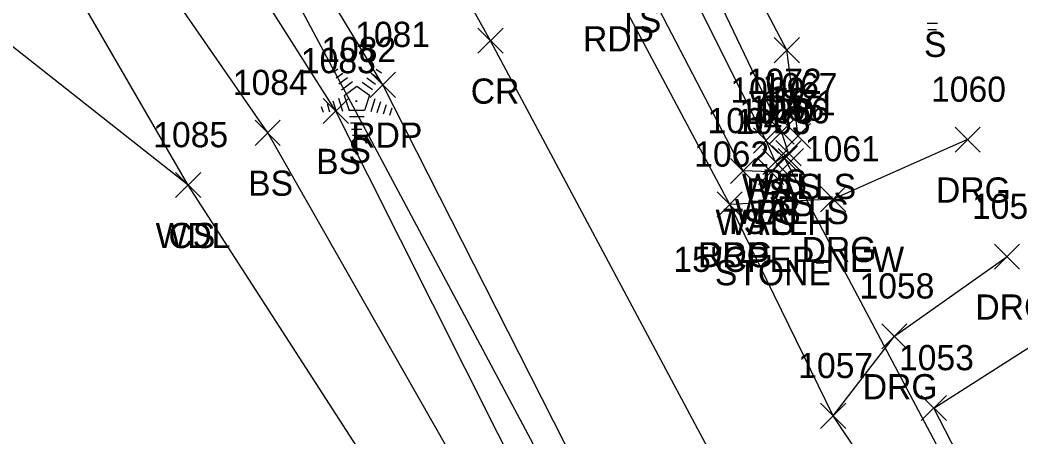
# Model space of a CAD drawing. Extents: x 1501299 to 1502485, y 381423 to 383765.
# Drawn here: x 1501851.9 to 1501931.5, y 382849.9 to 382883 of the extents above; entities that cross this region are included whole.
import ezdxf

# ---------------------------------------------------------------- set-up
doc = ezdxf.new("R2010")
doc.units = 0
for name, color, linetype in [('D_A', 7, 'Continuous'), ('D_C', 7, 'Continuous'), ('D_I', 7, 'Continuous'), ('D_TIC', 7, 'Continuous'), ('DCP', 7, 'Continuous'), ('L_A', 7, 'Continuous'), ('L_I', 7, 'Continuous'), ('L_TIC', 7, 'Continuous'), ('LAWA', 7, 'Continuous'), ('LELB', 7, 'Continuous'), ('LTC', 7, 'Continuous'), ('P_A', 7, 'Continuous'), ('P_I', 7, 'Continuous'), ('P_TIC', 7, 'Continuous'), ('PET', 7, 'Continuous'), ('PRC', 7, 'Continuous'), ('R_A', 7, 'Continuous'), ('R_I', 7, 'Continuous'), ('R_TIC', 7, 'Continuous'), ('RDG', 7, 'Continuous')]:
    doc.layers.add(name, color=color, linetype=linetype)

msp = doc.modelspace()

# ---------------------------------------------------------------- linework, layer by layer
at = {"layer": 'D_TIC'}
for points in [[(1501911.685, 382871.033), (1501913.685, 382873.033)], [(1501913.685, 382871.033), (1501911.685, 382873.033)], [(1501910.592, 382869.97), (1501912.592, 382871.97)], [(1501912.592, 382869.97), (1501910.592, 382871.97)]]:
    msp.add_lwpolyline(points, dxfattribs=at)
at = {"layer": 'DCP'}
msp.add_lwpolyline([(1501937.683, 382824.933), (1501912.685, 382872.033)], dxfattribs=at)
at = {"layer": 'L_TIC'}
for points in [[(1501911.85, 382879.639), (1501913.85, 382881.639)], [(1501913.85, 382879.639), (1501911.85, 382881.639)], [(1501876.018, 382874.801), (1501878.018, 382876.801)], [(1501878.018, 382874.801), (1501876.018, 382876.801)], [(1501870.615, 382873.073), (1501872.615, 382875.073)], [(1501872.615, 382873.073), (1501870.615, 382875.073)], [(1501910.192, 382872.468), (1501912.192, 382874.468)], [(1501912.192, 382872.468), (1501910.192, 382874.468)], [(1501910.192, 382872.468), (1501912.192, 382874.468)], [(1501912.192, 382872.468), (1501910.192, 382874.468)], [(1501911.438, 382873.164), (1501913.438, 382875.164)], [(1501913.438, 382873.164), (1501911.438, 382875.164)], [(1501912.743, 382872.819), (1501914.743, 382874.819)], [(1501914.743, 382872.819), (1501912.743, 382874.819)], [(1501912.743, 382872.819), (1501914.743, 382874.819)], [(1501914.743, 382872.819), (1501912.743, 382874.819)], [(1501911.981, 382871.458), (1501913.981, 382873.458)], [(1501913.981, 382871.458), (1501911.981, 382873.458)], [(1501910.937, 382870.769), (1501912.937, 382872.769)], [(1501912.937, 382870.769), (1501910.937, 382872.769)], [(1501912.172, 382870.822), (1501914.172, 382872.822)], [(1501914.172, 382870.822), (1501912.172, 382872.822)], [(1501908.37, 382870.043), (1501910.37, 382872.043)], [(1501910.37, 382870.043), (1501908.37, 382872.043)], [(1501910.592, 382869.97), (1501912.592, 382871.97)], [(1501912.592, 382869.97), (1501910.592, 382871.97)], [(1501864.291, 382868.925), (1501866.291, 382870.925)], [(1501866.291, 382868.925), (1501864.291, 382870.925)], [(1501864.291, 382868.925), (1501866.291, 382870.925)], [(1501866.291, 382868.925), (1501864.291, 382870.925)], [(1501923.534, 382851.229), (1501925.534, 382853.229)], [(1501925.534, 382851.229), (1501923.534, 382853.229)]]:
    msp.add_lwpolyline(points, dxfattribs=at)
at = {"layer": 'LAWA'}
msp.add_lwpolyline([(1501942.677, 382714.841), (1501935.183, 382744.721), (1501913.337, 382785.2), (1501893.395, 382826.433), (1501865.291, 382869.925), (1501854.75, 382888.13), (1501835.928, 382927.55), (1501822.234, 382953.468), (1501796.607, 382993.044), (1501779.613, 383024.31), (1501754.165, 383064.049), (1501733.525, 383095.142)], dxfattribs=at)
at = {"layer": 'LELB'}
for points in [[(1501947.071, 382716.202), (1501936.789, 382745.616), (1501921.74, 382787.499), (1501900.168, 382829.778), (1501877.018, 382875.801), (1501866.166, 382892.912), (1501844.624, 382932.733), (1501828.058, 382959.038), (1501805.265, 382995.601), (1501783.687, 383028.162), (1501760.133, 383067.523), (1501734.806, 383103.876), (1501716.067, 383128.727), (1501702.976, 383136.285), (1501694.191, 383132.723)], [(1501947.958, 382716.119), (1501939.996, 382745.704), (1501923.414, 382788.324), (1501902.81, 382830.435), (1501868.959, 382893.881), (1501846.402, 382933.734), (1501830.033, 382960.147), (1501806.634, 382996.692), (1501785.685, 383029.202), (1501761.094, 383068.04), (1501736.237, 383105.316), (1501718.865, 383131.579)], [(1501945.344, 382716.136), (1501936.673, 382745.194), (1501918.388, 382786.659), (1501897.882, 382827.989), (1501871.615, 382874.073), (1501860.416, 382890.256), (1501841.87, 382931.652), (1501826.472, 382956.951), (1501803.66, 382993.76), (1501782.057, 383026.726), (1501758.572, 383066.643), (1501733.616, 383102.86), (1501712.412, 383124.491), (1501694.918, 383122.167), (1501687.272, 383121.659)], [(1501865.291, 382869.925), (1501843.565, 382887.058), (1501825.248, 382920.855), (1501815.651, 382951.421), (1501792.133, 382984.558)], [(1501911.592, 382870.97), (1501909.37, 382871.043), (1501901.055, 382887.028), (1501890.021, 382905.247), (1501881.668, 382923.868), (1501887.244, 382925.863)], [(1501913.743, 382873.819), (1501912.85, 382880.639), (1501907.588, 382890.652), (1501896.712, 382908.113), (1501888.043, 382924.994), (1501887.244, 382925.863)], [(1501911.192, 382873.468), (1501903.441, 382888.957), (1501892.525, 382906.285), (1501883.724, 382924.051), (1501884.747, 382924.568)], [(1501911.192, 382873.468), (1501911.937, 382871.769), (1501912.981, 382872.458), (1501912.438, 382874.164), (1501905.102, 382889.525), (1501893.938, 382907.292), (1501884.747, 382924.568)], [(1501941.731, 382843.486), (1501929.997, 382841.568), (1501924.534, 382852.229), (1501934.692, 382858.695)]]:
    msp.add_lwpolyline(points, dxfattribs=at)
at = {"layer": 'LTC'}
for p, q in [((1501924.822, 382882.755), (1501923.99, 382882.755)), ((1501924.738, 382882.255), (1501924.063, 382882.255)), ((1501876.835, 382878.893), (1501877.189, 382879.151)), ((1501877.044, 382878.428), (1501877.574, 382878.812)), ((1501877.254, 382877.962), (1501877.958, 382878.473)), ((1501879.491, 382878.437), (1501880.17, 382877.943)), ((1501879.862, 382878.785), (1501880.412, 382878.386)), ((1501880.233, 382879.134), (1501880.652, 382878.829)), ((1501877.464, 382877.496), (1501878.342, 382878.134)), ((1501877.688, 382877.041), (1501878.7, 382877.776)), ((1501878.7, 382877.776), (1501879.697, 382877.051)), ((1501879.12, 382878.089), (1501879.929, 382877.5)), ((1501877.234, 382876.822), (1501877.564, 382875.803)), ((1501877.688, 382877.041), (1501878.075, 382875.848)), ((1501879.697, 382877.051), (1501879.306, 382875.848)), ((1501875.867, 382876.173), (1501876.019, 382875.705)), ((1501876.323, 382876.389), (1501876.534, 382875.738)), ((1501876.778, 382876.606), (1501877.049, 382875.771)), ((1501880.134, 382876.78), (1501879.797, 382875.741)), ((1501880.579, 382876.53), (1501880.292, 382875.645)), ((1501881.024, 382876.28), (1501880.787, 382875.55)), ((1501881.468, 382876.029), (1501881.281, 382875.455)), ((1501879.306, 382875.848), (1501878.075, 382875.848)), ((1501879.267, 382875.348), (1501878.123, 382875.348)), ((1501879.184, 382874.848), (1501878.195, 382874.848)), ((1501879.1, 382874.348), (1501878.268, 382874.348)), ((1501879.016, 382873.848), (1501878.341, 382873.848))]:
    msp.add_line(p, q, dxfattribs=at)
at = {"layer": 'P_TIC'}
for points in [[(1501888.309, 382880.383), (1501890.309, 382882.383)], [(1501890.309, 382880.383), (1501888.309, 382882.383)], [(1501879.763, 382876.887), (1501881.763, 382878.887)], [(1501881.763, 382876.887), (1501879.763, 382878.887)], [(1501907.311, 382867.386), (1501909.311, 382869.386)], [(1501909.311, 382867.386), (1501907.311, 382869.386)], [(1501915.528, 382850.603), (1501917.528, 382852.603)], [(1501917.528, 382850.603), (1501915.528, 382852.603)]]:
    msp.add_lwpolyline(points, dxfattribs=at)
at = {"layer": 'PET'}
for points in [[(1501949.648, 382716.507), (1501941.04, 382745.977), (1501925.012, 382788.592), (1501904.253, 382831.621), (1501880.763, 382877.887), (1501870.565, 382894.723), (1501847.406, 382934.273), (1501830.938, 382961.01), (1501807.981, 382997.987), (1501787.075, 383029.946), (1501762.257, 383068.782), (1501737.378, 383106.292), (1501722.895, 383129.668), (1501696.699, 383166.339)], [(1501971.372, 382720.654), (1501961.032, 382754.708), (1501942.926, 382798.84), (1501930.998, 382825.078), (1501924.576, 382839.599), (1501916.528, 382851.603), (1501908.311, 382868.386), (1501899.175, 382885.527), (1501887.899, 382904.195), (1501878.505, 382922.493), (1501869.738, 382936.529), (1501858.065, 382956.489), (1501847.469, 382974.349), (1501824.868, 383010.254), (1501802.294, 383043.804), (1501787.994, 383066.094), (1501768.484, 383096.751)]]:
    msp.add_lwpolyline(points, dxfattribs=at)
at = {"layer": 'PRC'}
msp.add_lwpolyline([(1501960.612, 382718.648), (1501950.96, 382750.482), (1501934.965, 382791.852), (1501913.074, 382836.935), (1501889.309, 382881.383), (1501879.244, 382899.507), (1501856.391, 382940.32), (1501839.674, 382966.998), (1501816.055, 383004.313), (1501794.783, 383036.247), (1501769.812, 383075.158), (1501745.791, 383111.558), (1501729.435, 383136.001), (1501711.236, 383163.535), (1501694.816, 383188.199), (1501683.547, 383204.004), (1501664.644, 383231.239), (1501639.517, 383268.342), (1501626.393, 383287.881)], dxfattribs=at)
at = {"layer": 'R_TIC'}
for points in [[(1501926.211, 382872.533), (1501928.211, 382874.533)], [(1501928.211, 382872.533), (1501926.211, 382874.533)], [(1501915.536, 382867.812), (1501917.536, 382869.812)], [(1501917.536, 382867.812), (1501915.536, 382869.812)], [(1501907.311, 382867.386), (1501909.311, 382869.386)], [(1501909.311, 382867.386), (1501907.311, 382869.386)], [(1501929.341, 382863.244), (1501931.341, 382865.244)], [(1501931.341, 382863.244), (1501929.341, 382865.244)], [(1501920.392, 382856.92), (1501922.392, 382858.92)], [(1501922.392, 382856.92), (1501920.392, 382858.92)], [(1501915.528, 382850.603), (1501917.528, 382852.603)], [(1501917.528, 382850.603), (1501915.528, 382852.603)]]:
    msp.add_lwpolyline(points, dxfattribs=at)
at = {"layer": 'RDG'}
for points in [[(1501927.211, 382873.533), (1501916.536, 382868.812), (1501908.311, 382868.386)], [(1501916.528, 382851.603), (1501921.392, 382857.92), (1501930.341, 382864.244)]]:
    msp.add_lwpolyline(points, dxfattribs=at)

# ---------------------------------------------------------------- texts
at = {"layer": 'D_A'}
for s, p in [('P', (1501912.062, 382867.033)), ('WALLH', (1501907.183, 382865.97))]:
    msp.add_text(s, height=2, dxfattribs=at).set_placement(p)
at = {"layer": 'D_C'}
for s, p in [('15"CPEP-NEW', (1501903.834, 382863.033)), ('STONE', (1501907.136, 382861.97))]:
    msp.add_text(s, height=2, dxfattribs=at).set_placement(p)
at = {"layer": 'D_I'}
for s, p in [('1065', (1501909.866, 382875.033)), ('1063', (1501908.774, 382873.97))]:
    msp.add_text(s, height=2, dxfattribs=at).set_placement(p)
at = {"layer": 'L_A'}
for s, p in [('TS', (1501899.464, 382882.028)), ('S', (1501923.747, 382880.092)), ('TS', (1501911.26, 382875.639)), ('S', (1501878.026, 382871.685)), ('BS', (1501875.459, 382870.801)), ('BS', (1501870.056, 382869.073)), ('WALLS', (1501909.286, 382868.819)), ('BS', (1501909.633, 382868.468)), ('BS', (1501909.633, 382868.468)), ('BS', (1501910.879, 382869.164)), ('TS', (1501912.153, 382868.819)), ('BS', (1501911.422, 382867.458)), ('WALLS', (1501908.716, 382866.822)), ('BS', (1501910.378, 382866.769)), ('TS', (1501907.78, 382866.043)), ('TS', (1501910.002, 382865.97)), ('WDL', (1501862.708, 382864.925)), ('CS', (1501863.732, 382864.925))]:
    msp.add_text(s, height=2, dxfattribs=at).set_placement(p)
at = {"layer": 'L_I'}
for s, p in [('1082', (1501875.868, 382879.685)), ('1083', (1501874.247, 382878.801)), ('1084', (1501868.843, 382877.073)), ('1069', (1501908.366, 382876.468)), ('1069', (1501908.366, 382876.468)), ('1072', (1501909.667, 382877.164)), ('1067', (1501910.924, 382876.819)), ('1067', (1501910.924, 382876.819)), ('1066', (1501910.298, 382874.822)), ('1071', (1501910.776, 382875.458)), ('1064', (1501906.551, 382874.043)), ('1070', (1501909.079, 382874.769)), ('1063', (1501908.774, 382873.97)), ('1085', (1501862.519, 382872.925)), ('1085', (1501862.519, 382872.925)), ('1053', (1501921.762, 382855.229))]:
    msp.add_text(s, height=2, dxfattribs=at).set_placement(p)
at = {"layer": 'LTC'}
msp.add_text('.', height=1.037, rotation=270, dxfattribs=at).set_placement((1501878.582, 382876.789))
at = {"layer": 'P_A'}
for s, p in [('RDP', (1501896.663, 382880.527)), ('CR', (1501887.742, 382876.383)), ('RDP', (1501878.251, 382872.887)), ('RDP', (1501905.799, 382863.386))]:
    msp.add_text(s, height=2, dxfattribs=at).set_placement(p)
at = {"layer": 'P_I'}
for s, p in [('1081', (1501878.558, 382880.887)), ('1062', (1501905.493, 382871.386)), ('1057', (1501913.757, 382854.603))]:
    msp.add_text(s, height=2, dxfattribs=at).set_placement(p)
at = {"layer": 'R_A'}
for p in [(1501924.699, 382868.533), (1501914.024, 382863.812), (1501905.799, 382863.386), (1501927.829, 382859.244), (1501918.88, 382852.92)]:
    msp.add_text('DRG', height=2, dxfattribs=at).set_placement(p)
at = {"layer": 'R_I'}
for s, p in [('1060', (1501924.306, 382876.533)), ('1061', (1501914.284, 382871.812)), ('1062', (1501905.493, 382871.386)), ('1059', (1501927.562, 382867.244)), ('1058', (1501918.621, 382860.92)), ('1057', (1501913.757, 382854.603))]:
    msp.add_text(s, height=2, dxfattribs=at).set_placement(p)

doc.saveas('drawing.dxf')
